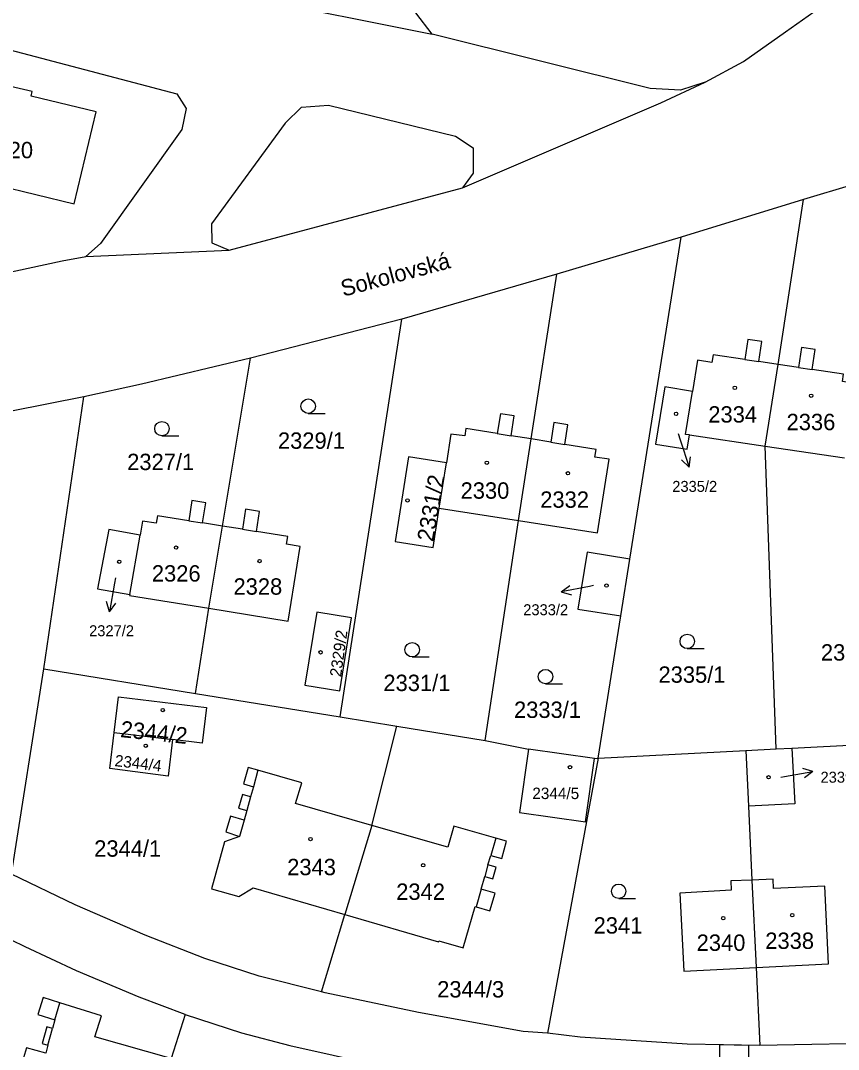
# Model space of a CAD drawing. Extents: x -869103 to -863415, y -1015889 to -1012477.
# Drawn here: x -866069.9 to -865985.1, y -1014951.6 to -1014844.8 of the extents above; entities that cross this region are included whole.
import ezdxf

# ---------------------------------------------------------------- set-up
doc = ezdxf.new("R2010")
doc.units = 0
for name, color, linetype in [('Hranice parcel', 7, 'Continuous'), ('Parcelní čísla', 7, 'Continuous'), ('Pop  PČ popisy', 7, 'Continuous'), ('Vnitřní kresba', 7, 'Continuous'), ('Věcná břemena k části', 7, 'Continuous'), ('Značky budov', 7, 'Continuous'), ('Značky kultur', 7, 'Continuous')]:
    doc.layers.add(name, color=color, linetype=linetype)

msp = doc.modelspace()

# ---------------------------------------------------------------- linework, layer by layer
at = {"layer": 'Hranice parcel'}
for p, q in [((-866049.3, -1014841.78), (-866027.2, -1014846.2)), ((-866064.35, -1014863.82), (-866062.06, -1014854.26)), ((-866080.24, -1014859.98), (-866064.35, -1014863.82)), ((-865983.6, -1014861.83), (-865988.7, -1014863.37)), ((-865988.7, -1014863.37), (-866001.39, -1014867.29)), ((-865991.3, -1014880.5), (-865988.7, -1014863.37)), ((-866001.39, -1014867.29), (-866014.26, -1014871.11)), ((-866006.71, -1014900.69), (-866001.39, -1014867.29)), ((-866065.6, -1014869.73), (-866063.15, -1014869.29)), ((-866014.26, -1014871.11), (-866030.35, -1014875.77)), ((-866016.95, -1014888.22), (-866014.26, -1014871.11)), ((-866030.35, -1014875.77), (-866046.06, -1014879.84)), ((-866036.75, -1014917.06), (-866030.35, -1014875.77)), ((-866048.95, -1014897.27), (-866046.06, -1014879.84)), ((-865999.68, -1014880.05), (-866000.2, -1014883.29)), ((-865992.67, -1014888.96), (-865991.3, -1014880.5)), ((-866067.49, -1014912.08), (-866063.33, -1014883.84)), ((-866025.27, -1014887.72), (-866025.73, -1014890.68)), ((-866018.26, -1014896.69), (-866016.95, -1014888.22)), ((-866000.51, -1014887.8), (-865992.67, -1014888.96)), ((-865991.52, -1014920.39), (-865992.67, -1014888.96)), ((-865992.67, -1014888.96), (-865984.42, -1014890.18)), ((-866026.47, -1014895.41), (-866025.73, -1014890.68)), ((-866026.47, -1014895.41), (-866018.26, -1014896.69)), ((-866057.25, -1014896.74), (-866057.51, -1014898.19)), ((-866021.72, -1014919.5), (-866018.26, -1014896.69)), ((-866050.38, -1014905.79), (-866048.95, -1014897.27)), ((-866058.59, -1014904.35), (-866057.51, -1014898.19)), ((-866007.65, -1014906.59), (-866006.71, -1014900.69)), ((-866051.75, -1014914.63), (-866050.38, -1014905.79)), ((-866010, -1014921.35), (-866007.65, -1014906.59)), ((-866070.84, -1014933.38), (-866067.49, -1014912.08)), ((-866067.49, -1014912.08), (-866051.75, -1014914.63)), ((-866051.75, -1014914.63), (-866036.75, -1014917.06)), ((-866036.75, -1014917.06), (-866030.86, -1014918.01)), ((-866033.48, -1014928.32), (-866030.86, -1014918.01)), ((-866030.86, -1014918.01), (-866021.72, -1014919.5)), ((-866060.19, -1014918.67), (-866054.14, -1014919.41)), ((-866021.72, -1014919.5), (-866017.23, -1014920.4)), ((-865991.52, -1014920.39), (-865989.89, -1014920.3)), ((-865989.89, -1014920.3), (-865973.25, -1014919.44)), ((-866010.37, -1014921.37), (-866017.23, -1014920.4)), ((-866010, -1014921.35), (-866015.24, -1014949.89)), ((-866010.37, -1014921.37), (-866010, -1014921.35)), ((-866010, -1014921.35), (-865994.67, -1014920.55)), ((-865994.67, -1014920.55), (-865991.52, -1014920.39)), ((-865994.67, -1014920.55), (-865994.4, -1014926.32)), ((-865994.4, -1014926.32), (-865994.03, -1014933.99)), ((-866033.48, -1014928.32), (-866036.27, -1014937.57)), ((-865994.03, -1014933.99), (-865996.24, -1014934.09)), ((-865991.84, -1014933.9), (-865994.03, -1014933.99)), ((-865994.03, -1014933.99), (-865993.6, -1014943.06)), ((-866038.69, -1014945.6), (-866036.27, -1014937.57)), ((-865993.6, -1014943.06), (-865993.23, -1014951.18)), ((-866038.69, -1014945.6), (-866045.16, -1014943.98)), ((-866052.82, -1014947.95), (-866054.3, -1014952.51))]:
    msp.add_line(p, q, dxfattribs=at)
for points in [[(-865998.88, -1014851.18), (-865994.92, -1014849.06), (-865990.56, -1014845.98), (-865980.57, -1014838.89), (-865974.46, -1014834.71), (-865936.65, -1014808.22), (-865929.51, -1014802.9), (-865885.66, -1014771.72), (-865853.7, -1014749.91)], [(-866027.2, -1014846.2), (-866028.9, -1014844.01), (-866028.57, -1014841.09), (-866013.17, -1014819.22)], [(-866119.75, -1014834.98), (-866053.69, -1014852.41), (-866052.73, -1014853.93), (-866053.17, -1014856.11), (-866061.63, -1014867.95), (-866063.15, -1014869.29)], [(-865998.88, -1014851.18), (-866001.43, -1014852.03), (-866004.6, -1014851.84), (-866027.2, -1014846.2)], [(-866062.06, -1014854.26), (-866068.82, -1014852.65), (-866068.71, -1014852.17), (-866071.41, -1014851.55), (-866071.52, -1014852.01), (-866077.94, -1014850.48)], [(-866024.06, -1014862.17), (-866003.48, -1014853.35), (-865998.88, -1014851.18)], [(-866063.15, -1014869.29), (-866048.26, -1014868.62), (-866024.06, -1014862.17)], [(-866130.04, -1014877.27), (-866119.09, -1014876.95), (-866108.14, -1014876.34), (-866092.5, -1014874.76), (-866081.8, -1014873.24), (-866065.6, -1014869.73)], [(-865991.3, -1014880.5), (-865993.33, -1014880.19), (-865993.02, -1014878.11), (-865994.46, -1014877.9), (-865994.77, -1014879.97), (-865998.07, -1014879.48), (-865998.19, -1014880.28), (-865999.68, -1014880.05)], [(-865983.15, -1014882.49), (-865984.64, -1014882.26), (-865984.53, -1014881.51), (-865987.8, -1014881.02), (-865987.49, -1014878.94), (-865988.9, -1014878.73), (-865989.21, -1014880.81), (-865991.3, -1014880.5)], [(-866046.06, -1014879.84), (-866057.38, -1014882.52), (-866063.33, -1014883.84)], [(-866000.2, -1014883.29), (-866003.07, -1014882.82), (-866004.04, -1014888.76), (-866000.75, -1014889.28), (-866000.51, -1014887.8)], [(-866063.33, -1014883.84), (-866070.85, -1014885.32), (-866079.71, -1014886.86)], [(-866000.51, -1014887.8), (-866000.92, -1014887.74), (-866000.2, -1014883.29)], [(-866016.95, -1014888.22), (-866019.03, -1014887.89), (-866018.7, -1014885.83), (-866020.12, -1014885.6), (-866020.45, -1014887.66), (-866023.7, -1014887.14), (-866023.82, -1014887.91), (-866025.27, -1014887.72)], [(-866008.84, -1014890.31), (-866010.32, -1014890.1), (-866010.19, -1014889.3), (-866013.45, -1014888.78), (-866013.13, -1014886.74), (-866014.57, -1014886.51), (-866014.89, -1014888.55), (-866016.95, -1014888.22)], [(-866025.73, -1014890.68), (-866029.68, -1014890.06), (-866031.06, -1014898.86), (-866027.1, -1014899.47), (-866026.47, -1014895.41)], [(-866018.26, -1014896.69), (-866010.05, -1014897.96), (-866008.84, -1014890.31)], [(-866048.95, -1014897.27), (-866051.04, -1014896.93), (-866050.7, -1014894.84), (-866052.13, -1014894.61), (-866052.47, -1014896.7), (-866055.7, -1014896.18), (-866055.83, -1014896.97), (-866057.25, -1014896.74)], [(-866040.89, -1014899.37), (-866042.32, -1014899.14), (-866042.19, -1014898.35), (-866045.45, -1014897.83), (-866045.12, -1014895.74), (-866046.56, -1014895.5), (-866046.89, -1014897.59), (-866048.95, -1014897.27)], [(-866057.51, -1014898.19), (-866060.75, -1014897.62), (-866061.93, -1014903.76), (-866058.59, -1014904.35)], [(-866050.38, -1014905.79), (-866042.15, -1014907.13), (-866040.89, -1014899.37)], [(-866006.71, -1014900.69), (-866011.13, -1014899.98), (-866012.09, -1014905.88), (-866007.65, -1014906.59)], [(-866058.59, -1014904.35), (-866058.61, -1014904.45), (-866050.38, -1014905.79)], [(-866036.78, -1014914.36), (-866035.57, -1014906.79), (-866039.17, -1014906.2), (-866040.41, -1014913.77), (-866036.78, -1014914.36)], [(-866060.19, -1014918.67), (-866059.74, -1014914.98), (-866050.63, -1014916.09), (-866051.08, -1014919.79), (-866054.14, -1014919.41)], [(-866054.14, -1014919.41), (-866054.6, -1014923.2), (-866060.65, -1014922.43), (-866060.19, -1014918.67)], [(-865989.89, -1014920.3), (-865989.6, -1014926.08), (-865994.4, -1014926.32)], [(-866017.23, -1014920.4), (-866018.15, -1014926.97), (-866011.29, -1014927.94), (-866010.37, -1014921.37)], [(-866033.48, -1014928.32), (-866041.37, -1014926.06), (-866040.74, -1014923.89), (-866045.28, -1014922.6), (-866046.3, -1014922.3), (-866046.79, -1014924.02), (-866045.75, -1014924.31), (-866046.04, -1014925.35), (-866046.87, -1014925.1), (-866047.29, -1014926.52), (-866046.43, -1014926.77), (-866046.71, -1014927.78), (-866048.14, -1014927.36), (-866048.62, -1014929), (-866047.18, -1014929.46)], [(-866022.66, -1014936.78), (-866021.21, -1014937.19), (-866020.69, -1014935.36), (-866022.14, -1014934.95), (-866021.76, -1014933.62), (-866020.91, -1014933.86), (-866020.57, -1014932.67), (-866021.42, -1014932.43), (-866021.13, -1014931.43), (-866019.97, -1014931.76), (-866019.48, -1014929.97), (-866020.62, -1014929.64), (-866024.97, -1014928.4), (-866025.59, -1014930.57), (-866033.48, -1014928.32)], [(-866047.18, -1014929.46), (-866048.76, -1014930.04), (-866050.11, -1014934.91), (-866047.28, -1014935.7), (-866045.77, -1014934.8), (-866036.27, -1014937.57)], [(-866045.16, -1014943.98), (-866050.8, -1014942.12), (-866057, -1014939.7), (-866064.26, -1014936.56), (-866070.84, -1014933.38)], [(-865996.24, -1014934.09), (-865996.2, -1014935.06), (-866001.5, -1014935.35)], [(-865986.46, -1014934.63), (-865991.8, -1014934.88), (-865991.84, -1014933.9)], [(-865993.6, -1014943.06), (-865986.09, -1014942.69), (-865986.46, -1014934.63)], [(-866001.5, -1014935.35), (-866001.11, -1014943.44), (-865993.6, -1014943.06)], [(-866036.27, -1014937.57), (-866026.56, -1014940.39), (-866026.53, -1014940.29), (-866023.98, -1014941.04), (-866022.76, -1014936.75), (-866022.66, -1014936.78)], [(-866052.82, -1014947.95), (-866057.6, -1014946.16), (-866064.1, -1014943.4), (-866069.43, -1014940.94), (-866075.13, -1014938.16)], [(-866015.24, -1014949.89), (-866017.78, -1014949.71), (-866028.61, -1014947.75), (-866038.31, -1014945.69), (-866038.69, -1014945.6)], [(-866054.3, -1014952.51), (-866062.19, -1014950.25), (-866061.51, -1014948.09), (-866065.85, -1014946.73), (-866067.58, -1014946.19), (-866068.13, -1014947.96), (-866066.35, -1014948.51), (-866066.59, -1014949.4), (-866067.2, -1014949.23), (-866067.68, -1014950.96), (-866067.07, -1014951.13), (-866067.3, -1014951.96), (-866069.3, -1014951.4), (-866069.81, -1014953.12), (-866067.79, -1014953.71), (-866065.19, -1014954.48), (-866066.51, -1014958.96), (-866058.52, -1014961.31)], [(-866052.82, -1014947.95), (-866046.98, -1014949.85), (-866041.99, -1014951.17), (-866032.98, -1014953.16), (-866029.71, -1014953.75)], [(-865993.23, -1014951.18), (-866000.75, -1014951.03), (-866011.84, -1014950.29), (-866015.24, -1014949.89)], [(-865972.03, -1014949.58), (-865974.81, -1014950.44), (-865978.81, -1014950.87), (-865993.23, -1014951.18)]]:
    msp.add_lwpolyline(points, dxfattribs=at)
at = {"layer": 'Pop  PČ popisy'}
for p, q in [((-866001.7, -1014887.64), (-866001.49, -1014888.31)), ((-866001.49, -1014888.31), (-866000.56, -1014891.16)), ((-866000.56, -1014891.16), (-866001.35, -1014890.37)), ((-866000.56, -1014891.16), (-866000.4, -1014890.06)), ((-866060.17, -1014903.19), (-866060.69, -1014906.15)), ((-866060.06, -1014902.62), (-866060.17, -1014903.19)), ((-866013.83, -1014904.1), (-866012.94, -1014903.42)), ((-866010.88, -1014903.53), (-866013.83, -1014904.1)), ((-866013.83, -1014904.1), (-866012.75, -1014904.4)), ((-866010.46, -1014903.44), (-866010.88, -1014903.53)), ((-866060.69, -1014906.15), (-866061.01, -1014905.07)), ((-866060.69, -1014906.15), (-866060.02, -1014905.25)), ((-865987.7, -1014922.73), (-865988.77, -1014922.41)), ((-865991.05, -1014923.32), (-865990.65, -1014923.25)), ((-865990.65, -1014923.25), (-865987.7, -1014922.73)), ((-865987.7, -1014922.73), (-865988.59, -1014923.4))]:
    msp.add_line(p, q, dxfattribs=at)
at = {"layer": 'Vnitřní kresba'}
for p, q in [((-866042.45, -1014855.43), (-866040.77, -1014853.77)), ((-866040.77, -1014853.77), (-866037.95, -1014853.57)), ((-866037.95, -1014853.57), (-866024.78, -1014856.78)), ((-866042.45, -1014855.43), (-866050.09, -1014865.9)), ((-866024.78, -1014856.78), (-866022.95, -1014858)), ((-866022.95, -1014858), (-866022.95, -1014860.65)), ((-866022.95, -1014860.65), (-866024.06, -1014862.17)), ((-866050.09, -1014865.9), (-866050.07, -1014867.88)), ((-866050.07, -1014867.88), (-866048.26, -1014868.62)), ((-865994.77, -1014879.97), (-865993.33, -1014880.19)), ((-865989.21, -1014880.81), (-865987.8, -1014881.02)), ((-866020.45, -1014887.66), (-866019.03, -1014887.89)), ((-866014.89, -1014888.55), (-866013.45, -1014888.78)), ((-866052.47, -1014896.7), (-866051.04, -1014896.93)), ((-866046.89, -1014897.59), (-866045.45, -1014897.83)), ((-866045.28, -1014922.6), (-866045.75, -1014924.31)), ((-866046.04, -1014925.35), (-866046.43, -1014926.77)), ((-866046.71, -1014927.78), (-866047.18, -1014929.46)), ((-866020.62, -1014929.64), (-866021.13, -1014931.43)), ((-866021.42, -1014932.43), (-866021.76, -1014933.62)), ((-866022.14, -1014934.95), (-866022.66, -1014936.78)), ((-866066.35, -1014948.51), (-866065.85, -1014946.73)), ((-866067.07, -1014951.13), (-866066.59, -1014949.4))]:
    msp.add_line(p, q, dxfattribs=at)
at = {"layer": 'Věcná břemena k části'}
msp.add_lwpolyline([(-865997.02, -1014956.24), (-865993.81, -1014956.42), (-865994.4, -1014954.62), (-865994.34, -1014951.16), (-865997.39, -1014951.1), (-865997.4, -1014955.08)], close=True, dxfattribs=at)
at = {"layer": 'Značky budov'}
for centre in [(-865995.81, -1014882.91), (-865987.89, -1014883.74), (-866001.9, -1014885.61), (-866021.54, -1014890.69), (-866013.13, -1014891.78), (-866029.77, -1014894.59), (-866053.78, -1014899.49), (-866059.67, -1014900.96), (-866045.11, -1014900.89), (-866009.12, -1014903.44), (-866038.79, -1014910.36), (-866055.16, -1014916.36), (-866056.92, -1014920.05), (-866012.91, -1014922.29), (-865992.31, -1014923.32), (-866039.83, -1014929.74), (-866028.14, -1014932.46), (-865989.85, -1014937.64), (-865997.01, -1014937.95)]:
    msp.add_circle(centre, 0.175, dxfattribs=at)
at = {"layer": 'Značky kultur'}
for p, q in [((-866040.07, -1014885.57), (-866038.32, -1014885.57)), ((-866055.24, -1014887.9), (-866053.49, -1014887.9)), ((-866000.74, -1014909.98), (-865998.99, -1014909.98)), ((-866029.28, -1014910.84), (-866027.53, -1014910.84)), ((-866015.45, -1014913.63), (-866013.7, -1014913.63)), ((-866007.86, -1014935.91), (-866006.11, -1014935.91))]:
    msp.add_line(p, q, dxfattribs=at)
for centre in [(-866040.07, -1014884.82), (-866055.24, -1014887.15), (-866000.74, -1014909.23), (-866029.28, -1014910.09), (-866015.45, -1014912.88), (-866007.86, -1014935.16)]:
    msp.add_circle(centre, 0.75, dxfattribs=at)

# ---------------------------------------------------------------- texts
at = {"layer": 'Parcelní čísla'}
for s, height, p in [('2220', 1.7, (-866073.67, -1014859.09)), ('2334', 1.7, (-865998.56, -1014886.52)), ('2336', 1.7, (-865990.44, -1014887.31)), ('2329/1', 1.7, (-866043.21, -1014889.24)), ('2327/1', 1.7, (-866058.85, -1014891.45)), ('2335/2', 1.139, (-866002.3, -1014893.71)), ('2330', 1.7, (-866024.26, -1014894.42)), ('2332', 1.7, (-866016, -1014895.36)), ('2326', 1.7, (-866056.29, -1014903.02)), ('2328', 1.7, (-866047.82, -1014904.38)), ('2333/2', 1.139, (-866017.76, -1014906.51)), ('2327/2', 1.139, (-866062.8, -1014908.69)), ('2337/1', 1.7, (-865986.88, -1014911.22)), ('2335/1', 1.7, (-866003.73, -1014913.52)), ('2331/1', 1.7, (-866032.27, -1014914.38)), ('2333/1', 1.7, (-866018.72, -1014917.17)), ('2339/2', 1.139, (-865986.92, -1014923.89)), ('2344/5', 1.19, (-866016.82, -1014925.59)), ('2344/1', 1.7, (-866062.27, -1014931.57)), ('2343', 1.7, (-866042.25, -1014933.49)), ('2342', 1.7, (-866030.94, -1014936.05)), ('2341', 1.7, (-866010.46, -1014939.55)), ('2338', 1.7, (-865992.65, -1014941.14)), ('2340', 1.7, (-865999.77, -1014941.34)), ('2344/3', 1.7, (-866026.69, -1014946.18))]:
    msp.add_text(s, height=height, dxfattribs=at).set_placement(p)
for s, height, rotation, p in [('2331/2', 1.7, 80, (-866027.11, -1014898.95)), ('2329/2', 1.19, 82, (-866036.66, -1014912.96)), ('2344/2', 1.7, 354, (-866059.61, -1014919.15)), ('2344/4', 1.19, 353, (-866060.19, -1014922.16))]:
    msp.add_text(s, height=height, rotation=rotation, dxfattribs=at).set_placement(p)
at = {"layer": 'Pop  PČ popisy'}
msp.add_text('Sokolovská', height=1.7, rotation=15, dxfattribs=at).set_placement((-866036.43, -1014873.47))

doc.saveas('drawing.dxf')
